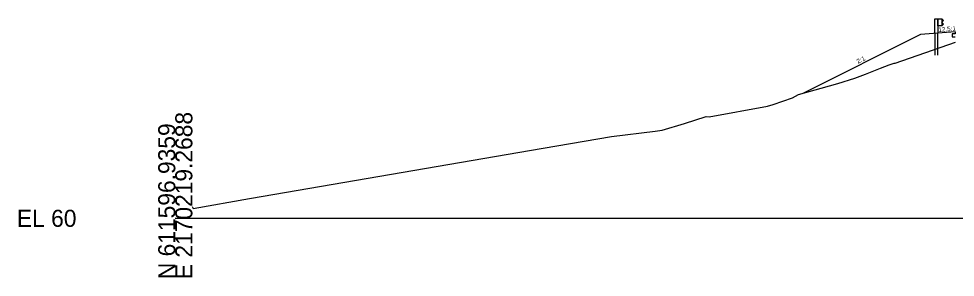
# Model space of a CAD drawing. Extents: x -26 to 1303, y -3010 to 12038.
# Drawn here: x 974.3 to 1128, y 1490.3 to 1532.8 of the extents above; entities that cross this region are included whole.
import ezdxf

# ---------------------------------------------------------------- set-up
doc = ezdxf.new("R2010")
doc.units = 0
for name, color, linetype in [('RD_GPK_XS_Cell', 7, 'Continuous'), ('RD_PD_Final_TrvlWay', 7, 'Continuous'), ('RD_XS_Base', 7, 'Continuous'), ('RD_XS_ExGround', 7, 'Continuous'), ('RD_XS_GR', 7, 'Continuous'), ('RD_XS_Greenside', 7, 'Continuous'), ('RD_XS_Pave', 7, 'Continuous'), ('RD_XS_TieSlope', 7, 'Continuous'), ('RD_XS_TX_ShdSlope', 7, 'Continuous'), ('RD_XS_TX_Slope', 7, 'Continuous')]:
    doc.layers.add(name, color=color, linetype=linetype)

msp = doc.modelspace()

# ---------------------------------------------------------------- linework, layer by layer
at = {"layer": 'RD_GPK_XS_Cell'}
msp.add_line((1000, 1500), (1150, 1500), dxfattribs=at)
at = {"layer": 'RD_PD_Final_TrvlWay'}
for p, q in [((1125.13, 1530.41), (1124.63, 1530.37)), ((1124.63, 1530.37), (1124.63, 1526.81)), ((1125.13, 1526.81), (1125.13, 1530.41))]:
    msp.add_line(p, q, dxfattribs=at)
at = {"layer": 'RD_XS_Base'}
for p, q in [((1128, 1530.32), (1127.5, 1530.3)), ((1127.5, 1530.3), (1127.5, 1530.3)), ((1127.5, 1530.3), (1127.5, 1529.8)), ((1127.5, 1529.8), (1128, 1529.82)), ((1128, 1530.32), (1128, 1530.32)), ((1128, 1529.82), (1128, 1529.82))]:
    msp.add_line(p, q, dxfattribs=at)
at = {"layer": 'RD_XS_ExGround'}
msp.add_lwpolyline([(1002.77, 1501.92), (1002.95, 1501.63), (1012.17, 1503.23), (1020.18, 1504.61), (1058.12, 1511.15), (1071.59, 1513.47), (1078.73, 1514.35), (1079.89, 1514.49), (1083.54, 1515.57), (1087.11, 1516.73), (1087.6, 1516.69), (1097.19, 1518.42), (1098.11, 1518.73), (1101.3, 1519.8), (1102.25, 1520.34), (1108.73, 1522.18), (1111.52, 1523.04), (1113.26, 1523.68), (1115.75, 1524.67), (1117.15, 1525.2), (1117.97, 1525.48), (1118.11, 1525.49), (1128.05, 1528.95)], dxfattribs=at)
at = {"layer": 'RD_XS_GR'}
for points in [[(1125.13, 1532.81), (1125.13, 1530.41), (1124.63, 1530.37), (1124.63, 1532.81), (1124.88, 1532.81), (1125.13, 1532.81)], [(1125.79, 1532.81), (1125.79, 1531.64), (1125.13, 1531.64), (1125.13, 1532.81), (1125.79, 1532.81)], [(1125.79, 1532.81), (1125.79, 1532.81), (1125.79, 1532.81), (1125.79, 1531.64), (1126.06, 1531.93), (1126.06, 1531.93), (1125.79, 1532.22), (1125.79, 1532.22), (1126.06, 1532.51), (1126.06, 1532.51), (1125.79, 1532.81)]]:
    msp.add_lwpolyline(points, dxfattribs=at)
at = {"layer": 'RD_XS_Greenside'}
msp.add_line((1122.31, 1530.19), (1103.1, 1520.58), dxfattribs=at)
at = {"layer": 'RD_XS_Pave'}
for p, q in [((1128, 1530.64), (1128, 1530.64)), ((1128, 1530.64), (1128, 1530.48)), ((1128, 1530.48), (1128, 1530.48)), ((1128, 1530.48), (1128, 1530.32))]:
    msp.add_line(p, q, dxfattribs=at)
at = {"layer": 'RD_XS_TieSlope'}
msp.add_line((1128, 1530.64), (1122.31, 1530.19), dxfattribs=at)

# ---------------------------------------------------------------- texts
at = {"layer": 'RD_GPK_XS_Cell'}
for s, p in [('E 2170219.2688', (1002.8, 1490)), ('N 611596.9359', (1000, 1490))]:
    msp.add_text(s, height=2.8, rotation=90, dxfattribs=at).set_placement(p)
msp.add_text('EL 60', height=2.8, dxfattribs=at).set_placement((974, 1498.6))
at = {"layer": 'RD_XS_TX_ShdSlope'}
msp.add_text('12.5:1', height=0.75, rotation=4.5739, dxfattribs=at).set_placement((1125.26, 1530.61))
at = {"layer": 'RD_XS_TX_Slope'}
msp.add_text('2:1', height=0.75, rotation=26.5651, dxfattribs=at).set_placement((1112.04, 1525.4))

doc.saveas('drawing.dxf')
